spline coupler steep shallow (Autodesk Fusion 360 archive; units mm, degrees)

design "spline coupler steep shallow" references "Haas UMC-750 NGC"
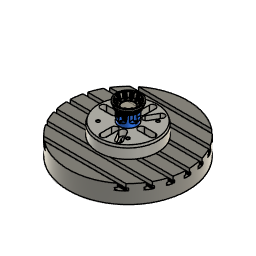
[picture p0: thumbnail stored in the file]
sketch "Sketch1" plane through (0, 0, 0) normal (1, 0, 0) x axis (0, 1, 0)
  line L1 (50.8, 0) -> (0, 0)
  line L2 (50.8, 25.4) -> (50.8, 0)
  line L3 (44.45, 25.4) -> (50.8, 25.4)
  line L4 (37.5164, 6.35) -> (44.45, 25.4)
  line L5 (0, 6.35) -> (37.5164, 6.35)
  line L6 (0, 0) -> (0, 6.35)
  line L7 (50.8, 19.05) -> (50.8, 25.4)
  line L8 (43.8664, 0) -> (50.8, 19.05)
  line L9 (48.0144, 13.7174) -> (48.4888, 12.7)
  line L10 (49.0317, 14.1918) -> (48.0144, 13.7174)
  line L11 (48.7603, 13.4459) -> (48.0144, 13.7174)
  line L12 (46.1776, 6.35) -> (47.0031, 6.35)
  circle C1 centre (48.9975, 12.9372) radius 0.5613
  circle C2 centre (47.0031, 6.35) radius 1.5875
  point P1 (0, 0)
  point P2 (0, 0)
  point P8 (0, 0)
  point P9 (50.8, 19.05)
  point P10 (43.8664, 0)
  point P11 (48.4888, 12.7)
  point P13 (49.0317, 14.1918)
  point P14 (48.7603, 13.4459)
  point P16 (48.4888, 12.7)
  point P17 (48.7603, 13.4459)
  point P18 (47.0031, 6.35)
  point P19 (47.0031, 6.35)
  point P20 (46.1776, 6.35)
  point P3 (50.8, 0)
  point P4 (50.8, 25.4)
  point P7 (0, 6.35)
  point P12 (48.0144, 13.7174)
  point P5 (44.45, 25.4)
  coincident P1 P2
  horizontal L1
  perpendicular L1 L2
  perpendicular L2 L3
  parallel L1 L5
  coincident P1 P8
  vertical L6
  coincident L2 P9
  coincident L1 P10
  parallel L4 L8
  coincident L8 P11
  coincident L8 P13
  perpendicular L9 L10
  equal L9 L10
  coincident L8 P14
  perpendicular L8 L11
  coincident C1 P16
  coincident L8 P16
  coincident P11 P16
  coincident C1 P17
  coincident P14 P17
  tangent L9 C1
  coincident P18 P19
  coincident L8 P20
  horizontal L12
  dimension "d2" = 88.9
  dimension "d3" distance P3 P4 = 25.4
  dimension "d4" angle L3 L4 = 70
  dimension "d5" distance P7 P8 = 6.35
  dimension "d37" distance P4 P9 = 6.35
  dimension "d38" distance P12 P14 = 0.7937
  dimension "d39" distance P10 P11 = 12.7
  dimension "d40" distance P4 P5 = 6.35
  dimension "d43" diameter C2 = 3.175
  dimension "d44" distance L1 P18 = 6.35
  dimension "d45" distance P19 P20 = 0.8255
revolve "Revolve1" sketch "Sketch1" AlongAngle 360
work_plane "WorkPlane1" AlongDistance -3.175
sketch "Sketch2" plane through (0, 0, 22.225) normal (0, 0, 1) x axis (1, 0, 0)
  line L1 (0, 36.9444) -> (0, 0)
  line L2 (3.175, 36.9444) -> (-3.175, 36.9444)
  line L3 (3.175, 32.5535) -> (3.175, 36.9444)
  circle C1 centre (0, 0) radius 43.2944
  circle C2 centre (0, 0) radius 36.9444
  arc A1 centre (10.795, 36.9444) radius 7.62 clockwise from (3.175, 36.9444) to (6.0106, 42.8751)
  arc A2 centre (-10.795, 36.9444) radius 7.62 clockwise from (-6.0106, 42.8751) to (-3.175, 36.9444)
  point P2 (0, 0)
  point P4 (0, 0)
  point P5 (0, 36.9444)
  point P8 (6.0106, 42.8751)
  point P7 (3.175, 36.9444)
  point P13 (-3.175, 36.9444)
  point P12 (-6.0106, 42.8751)
  point P6 (-3.175, 36.9444)
  coincident P2 P4
  coincident C2 P5
  vertical L1
  perpendicular L1 L2
  midpoint P5 L2
  coincident C1 P8
  perpendicular L2 L3
  tangent A1 L3
  symmetric L1 P7 P13
  symmetric L1 P8 P12
  symmetric L1 A1 A2
  dimension "d8" = 6.35
  dimension "d9" distance P6 P7 = 6.35
  dimension "d10" radius A1 = 7.62
sketch "Sketch3" plane through (0, 0, 22.225) normal (0, 0, 1) x axis (1, 0, 0)
sketch "Sketch4" plane through (0, 0, 0) normal (1, 0, 0) x axis (0, 1, 0)
  line L1 (37.5164, 6.35) -> (44.45, 25.4)
  line L2 (-44.45, 25.4) -> (-37.5164, 6.35)
  line L3 (36.9444, 22.225) -> (0, 22.225)
  line L4 (31.1664, 6.35) -> (36.9444, 22.225)
  line L5 (-37.5164, 6.35) -> (37.5164, 6.35)
  point P7 (36.9444, 22.225)
  point P8 (36.9444, 22.225)
  point P9 (31.1664, 6.35)
  coincident P7 P8
  coincident P9 L5
  parallel L1 L4
copy_paste_bodies "CopyPasteBodies2"
sweep "Sweep1" sketch "Sketch2" TwistAngle 0 TaperAngle 0
fillet "Fillet1" sketch "Sketch1" radius 1.5875
fillet "Fillet5" sketch "Sketch1" radius 1.5875
circular_pattern "C-Pattern1" countU 12 TotalAngle 360
fillet "Fillet2" radius 1.5875
fillet "Fillet4" radius 1.5875
sketch "Sketch5" plane through (0, 0, 6.35) normal (0, 0, 1) x axis (-1, 0, 0)
  curve K1 (12.3507, -34.2457) -> (12.1885, -30.8252)
  line L1 (16.5345, -25.1581) -> (13.5203, -26.8984)
  curve K2 (20.6012, -25.9681) -> (23.4823, -27.8189)
  curve K3 (27.8189, -23.4823) -> (25.9681, -20.6012)
  line L2 (26.8984, -13.5203) -> (25.1581, -16.5345)
  curve K4 (30.8252, -12.1885) -> (34.2457, -12.3507)
  curve K5 (35.833, -6.4268) -> (32.7897, -4.8571)
  line L3 (30.0548, 1.7403) -> (30.0548, -1.7403)
  curve K6 (32.7897, 4.8571) -> (35.833, 6.4268)
  curve K7 (34.2457, 12.3507) -> (30.8252, 12.1885)
  line L4 (25.1581, 16.5345) -> (26.8984, 13.5203)
  curve K8 (25.9681, 20.6012) -> (27.8189, 23.4823)
  curve K9 (23.4823, 27.8189) -> (20.6012, 25.9681)
  line L5 (13.5203, 26.8984) -> (16.5345, 25.1581)
  curve K10 (12.1885, 30.8252) -> (12.3507, 34.2457)
  curve K11 (6.4268, 35.833) -> (4.8571, 32.7897)
  line L6 (-1.7403, 30.0548) -> (1.7403, 30.0548)
  curve K12 (-4.8571, 32.7897) -> (-6.4268, 35.833)
  curve K13 (-12.3507, 34.2457) -> (-12.1885, 30.8252)
  line L7 (-16.5345, 25.1581) -> (-13.5203, 26.8984)
  curve K14 (-20.6012, 25.9681) -> (-23.4823, 27.8189)
  curve K15 (-27.8189, 23.4823) -> (-25.9681, 20.6012)
  line L8 (-26.8984, 13.5203) -> (-25.1581, 16.5345)
  curve K16 (-30.8252, 12.1885) -> (-34.2457, 12.3507)
  curve K17 (-35.833, 6.4268) -> (-32.7897, 4.8571)
  line L9 (-30.0548, -1.7403) -> (-30.0548, 1.7403)
  curve K18 (-32.7897, -4.8571) -> (-35.833, -6.4268)
  curve K19 (-34.2457, -12.3507) -> (-30.8252, -12.1885)
  line L10 (-25.1581, -16.5345) -> (-26.8984, -13.5203)
  curve K20 (-25.9681, -20.6012) -> (-27.8189, -23.4823)
  curve K21 (-23.4823, -27.8189) -> (-20.6012, -25.9681)
  line L11 (-13.5203, -26.8984) -> (-16.5345, -25.1581)
  curve K22 (-12.1885, -30.8252) -> (-12.3507, -34.2457)
  curve K23 (-6.4268, -35.833) -> (-4.8571, -32.7897)
  line L12 (1.7403, -30.0548) -> (-1.7403, -30.0548)
  curve K24 (4.8571, -32.7897) -> (6.4268, -35.833)
  closed curve K25 centre (15.2096, -29.8245)
  closed curve K26 centre (18.2239, -28.0842)
  arc A1 centre (0, 0) radius 36.4048 clockwise from (27.8189, -23.4823) to (23.4823, -27.8189)
  closed curve K27 centre (28.0842, -18.2239)
  closed curve K28 centre (29.8245, -15.2096)
  arc A2 centre (0, 0) radius 36.4048 clockwise from (35.833, -6.4268) to (34.2457, -12.3507)
  closed curve K29 centre (33.4336, -1.7403)
  closed curve K30 centre (33.4336, 1.7403)
  arc A3 centre (0, 0) radius 36.4048 clockwise from (34.2457, 12.3507) to (35.833, 6.4268)
  closed curve K31 centre (29.8245, 15.2096)
  closed curve K32 centre (28.0842, 18.2239)
  arc A4 centre (0, 0) radius 36.4048 clockwise from (23.4823, 27.8189) to (27.8189, 23.4823)
  closed curve K33 centre (18.2239, 28.0842)
  closed curve K34 centre (15.2096, 29.8245)
  arc A5 centre (0, 0) radius 36.4048 clockwise from (6.4268, 35.833) to (12.3507, 34.2457)
  closed curve K35 centre (1.7403, 33.4336)
  closed curve K36 centre (-1.7403, 33.4336)
  arc A6 centre (0, 0) radius 36.4048 clockwise from (-12.3507, 34.2457) to (-6.4268, 35.833)
  closed curve K37 centre (-15.2096, 29.8245)
  closed curve K38 centre (-18.2239, 28.0842)
  arc A7 centre (0, 0) radius 36.4048 clockwise from (-27.8189, 23.4823) to (-23.4823, 27.8189)
  closed curve K39 centre (-28.0842, 18.2239)
  closed curve K40 centre (-29.8245, 15.2096)
  arc A8 centre (0, 0) radius 36.4048 clockwise from (-35.833, 6.4268) to (-34.2457, 12.3507)
  closed curve K41 centre (-33.4336, 1.7403)
  closed curve K42 centre (-33.4336, -1.7403)
  arc A9 centre (0, 0) radius 36.4048 clockwise from (-34.2457, -12.3507) to (-35.833, -6.4268)
  closed curve K43 centre (-29.8245, -15.2096)
  closed curve K44 centre (-28.0842, -18.2239)
  arc A10 centre (0, 0) radius 36.4048 clockwise from (-23.4823, -27.8189) to (-27.8189, -23.4823)
  closed curve K45 centre (-18.2239, -28.0842)
  closed curve K46 centre (-15.2096, -29.8245)
  arc A11 centre (0, 0) radius 36.4048 clockwise from (-6.4268, -35.833) to (-12.3507, -34.2457)
  closed curve K47 centre (-1.7403, -33.4336)
  closed curve K48 centre (1.7403, -33.4336)
  arc A12 centre (0, 0) radius 36.4048 clockwise from (12.3507, -34.2457) to (6.4268, -35.833)
  circle C1 centre (0, 0) radius 25.4
  concentric A1 C1
  dimension "d29" diameter C1 = 50.8
extrude "Extrude1" cut sketch "Sketch5" profile of C1 against normal blind 3.175
chamfer "Chamfer1" sketch "Sketch1" distance 0.7937
fillet "Fillet6" sketch "Sketch1" radius 1.5875
delete_face "DeleteFace1"
delete_face "DeleteFace2"
delete_face "DeleteFace3"
derived_base_feature "Derived Base Feature1" bodies "Dovetail"
move "Move1"
offset_faces "OffsetFaces1" distance -25.4
move "Move2"
align "Align1"
combine "Combine2" bodies "Dovetail"
derived_base_feature "Derived Base Feature1" bodies "Body1"
base_feature "Base Feature1"
joint "Assemble1" alignAngle 0 alignOffsetX 0 named "d2_1" alignOffsetY 0 named "d3_1" alignOffsetZ 0 named "d4_1"
base_feature "Base Feature1" bodies "Body1", "Body2", "Body3", "Body4", "Body5", "Body6"
joint "Assemble2" alignAngle 0 named "d5_1" alignOffsetX 0 named "d6_1" alignOffsetY 0 named "d7_1" alignOffsetZ 0 named "d8_1"
joint "Assemble1" alignAngle 0 alignOffsetX 0 alignOffsetY 0 alignOffsetZ 0
sketch "Sketch7" plane through (0, 0, 0) normal (1, 0, 0) x axis (0, 1, 0)
  line L1 (-251.1903, -101.5746) -> (-198.6319, -101.5746)
  point P1 (0, 0)
  point P2 (0, -355.5746)
  vertical P1 P2
  dimension "d51" distance P2 L1 = 254
work_point "WorkPoint1"
sketch "Dovetail" plane through (0, 0, 0) normal (1, 0, 0) x axis (0, 1, 0)
  line L1 (-18.5336, -2.3876) -> (-17.1551, 0)
  line L2 (-18.5336, -3.1496) -> (-18.5336, -2.3876)
  line L3 (-23.5051, 0) -> (-17.1551, 0)
  line L4 (-23.5051, -50.8) -> (-23.5051, 0)
  line L5 (-18.5336, -50.8) -> (-23.5051, -50.8)
  line L6 (-18.5336, -3.1496) -> (-18.5336, -50.8)
  point P2 (-17.1551, 0)
  point P6 (-17.1551, 0)
  point P5 (-18.5336, -3.1496)
  point P10 (-18.5336, -3.1496)
  point P7 (-23.5051, 0)
  point P8 (-23.5051, -50.8)
  coincident P2 P6
  horizontal L3
  perpendicular L3 L4
  perpendicular L4 L5
  coincident P5 P10
  vertical L6
  dimension "d52" = 12.7
  dimension "d53" distance P7 P8 = 50.8
sketch "Sketch9" plane through (0, 0, 0) normal (1, 0, 0) x axis (0, 1, 0)
  line L1 (31.5465, 7.3945) -> (36.5642, 21.1805)
revolve "Revolve3" AlongAngle 360
component_insert "Component Insert"
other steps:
base_feature "Base Feature2" bodies "Stock"
joint_origin "JointOrigin1"
create_component "CreateComponent1"
joint_origin "JointOrigin1"
create_component "CreateComponent2"
create_component "CreateComponent2"
create_component "CreateComponent3"
named bodies: "Part", "Stock", "Dovetail", "Body1", "Body2", "Body3", "Body4", "Body5", "Body6"

design "Haas UMC-750 NGC"
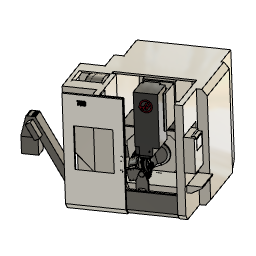
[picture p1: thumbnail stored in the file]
base_feature "Base Feature1"
base_feature "Base Feature1"
base_feature "Base Feature1"
base_feature "Base Feature1"
base_feature "Base Feature1"
base_feature "Base Feature1"
base_feature "Base Feature1"
base_feature "Base Feature1"
base_feature "Base Feature1" bodies "Body1"
base_feature "Base Feature1"
base_feature "Base Feature1" bodies "Body1", "Body2", "Body3", "Body4", "Body5", "Body6"
joint "Assemble1" alignAngle 0 alignOffsetX 0 alignOffsetY 0 alignOffsetZ 0
joint "Assemble2" alignAngle 0 alignOffsetX 0 alignOffsetY 0 alignOffsetZ 0
as_built_joint "As-built1"
as_built_joint "As-built2" OffsetX 0 OffsetY 0 OffsetZ 0 AngleZ 0
as_built_joint "As-built3" OffsetX 0 OffsetY 0 OffsetZ 0 AngleZ 0
ground "Ground1"
ground "Ground2"
sketch "Sketch1" plane through (0, 0, 0) normal (1, 0, 0) x axis (0, 1, 0)
  line L1 (50.8, 0) -> (0, 0)
  line L2 (50.8, 25.4) -> (50.8, 0)
  line L3 (44.45, 25.4) -> (50.8, 25.4)
  line L4 (37.5164, 6.35) -> (44.45, 25.4)
  line L5 (0, 6.35) -> (37.5164, 6.35)
  line L6 (0, 0) -> (0, 6.35)
  line L7 (50.8, 19.05) -> (50.8, 25.4)
  line L8 (43.8664, 0) -> (50.8, 19.05)
  line L9 (48.0144, 13.7174) -> (48.4888, 12.7)
  line L10 (49.0317, 14.1918) -> (48.0144, 13.7174)
  line L11 (48.7603, 13.4459) -> (48.0144, 13.7174)
  line L12 (46.1776, 6.35) -> (47.0031, 6.35)
  circle C1 centre (48.9975, 12.9372) radius 0.5613
  circle C2 centre (47.0031, 6.35) radius 1.5875
  point P1 (0, 0)
  point P2 (0, 0)
  point P8 (0, 0)
  point P9 (50.8, 19.05)
  point P10 (43.8664, 0)
  point P11 (48.4888, 12.7)
  point P13 (49.0317, 14.1918)
  point P14 (48.7603, 13.4459)
  point P16 (48.4888, 12.7)
  point P17 (48.7603, 13.4459)
  point P18 (47.0031, 6.35)
  point P19 (47.0031, 6.35)
  point P20 (46.1776, 6.35)
  point P3 (50.8, 0)
  point P4 (50.8, 25.4)
  point P7 (0, 6.35)
  point P12 (48.0144, 13.7174)
  point P5 (44.45, 25.4)
  coincident P1 P2
  horizontal L1
  perpendicular L1 L2
  perpendicular L2 L3
  parallel L1 L5
  coincident P1 P8
  vertical L6
  coincident L2 P9
  coincident L1 P10
  parallel L4 L8
  coincident L8 P11
  coincident L8 P13
  perpendicular L9 L10
  equal L9 L10
  coincident L8 P14
  perpendicular L8 L11
  coincident C1 P16
  coincident L8 P16
  coincident P11 P16
  coincident C1 P17
  coincident P14 P17
  tangent L9 C1
  coincident P18 P19
  coincident L8 P20
  horizontal L12
  dimension "d2_1" = 88.9
  dimension "d3_1" distance P3 P4 = 25.4
  dimension "d4_1" angle L3 L4 = 70
  dimension "d5_1" distance P7 P8 = 6.35
  dimension "d37" distance P4 P9 = 6.35
  dimension "d38" distance P12 P14 = 0.7937
  dimension "d39" distance P10 P11 = 12.7
  dimension "d40" distance P4 P5 = 6.35
  dimension "d43" diameter C2 = 3.175
  dimension "d44" distance L1 P18 = 6.35
  dimension "d45" distance P19 P20 = 0.8255
revolve "Revolve1" sketch "Sketch1" AlongAngle 360 named "d6_1"
work_plane "WorkPlane1" AlongDistance -3.175 named "d7_1"
sketch "Sketch2" plane through (0, 0, 22.225) normal (0, 0, 1) x axis (1, 0, 0)
  line L1 (0, 36.9444) -> (0, 0)
  line L2 (3.175, 36.9444) -> (-3.175, 36.9444)
  line L3 (3.175, 32.5535) -> (3.175, 36.9444)
  circle C1 centre (0, 0) radius 43.2944
  circle C2 centre (0, 0) radius 36.9444
  arc A1 centre (10.795, 36.9444) radius 7.62 clockwise from (3.175, 36.9444) to (6.0106, 42.8751)
  arc A2 centre (-10.795, 36.9444) radius 7.62 clockwise from (-6.0106, 42.8751) to (-3.175, 36.9444)
  point P2 (0, 0)
  point P4 (0, 0)
  point P5 (0, 36.9444)
  point P8 (6.0106, 42.8751)
  point P7 (3.175, 36.9444)
  point P13 (-3.175, 36.9444)
  point P12 (-6.0106, 42.8751)
  point P6 (-3.175, 36.9444)
  coincident P2 P4
  coincident C2 P5
  vertical L1
  perpendicular L1 L2
  midpoint P5 L2
  coincident C1 P8
  perpendicular L2 L3
  tangent A1 L3
  symmetric L1 P7 P13
  symmetric L1 P8 P12
  symmetric L1 A1 A2
  dimension "d8_1" = 6.35
  dimension "d9_1" distance P6 P7 = 6.35
  dimension "d10_1" radius A1 = 7.62
sketch "Sketch3" plane through (0, 0, 22.225) normal (0, 0, 1) x axis (1, 0, 0)
sketch "Sketch4" plane through (0, 0, 0) normal (1, 0, 0) x axis (0, 1, 0)
  line L1 (37.5164, 6.35) -> (44.45, 25.4)
  line L2 (-44.45, 25.4) -> (-37.5164, 6.35)
  line L3 (36.9444, 22.225) -> (0, 22.225)
  line L4 (31.1664, 6.35) -> (36.9444, 22.225)
  line L5 (-37.5164, 6.35) -> (37.5164, 6.35)
  point P7 (36.9444, 22.225)
  point P8 (36.9444, 22.225)
  point P9 (31.1664, 6.35)
  coincident P7 P8
  coincident P9 L5
  parallel L1 L4
copy_paste_bodies "CopyPasteBodies2"
sweep "Sweep1" sketch "Sketch2" TwistAngle 0 named "d15_1" TaperAngle 0 named "d16_1"
fillet "Fillet1" radius 1.5875
fillet "Fillet5" radius 1.5875
circular_pattern "C-Pattern1" countU 12 TotalAngle 360
fillet "Fillet2" radius 1.5875
fillet "Fillet4" radius 1.5875
sketch "Sketch5" plane through (0, 0, 6.35) normal (0, 0, 1) x axis (-1, 0, 0)
  curve K1 (12.3507, -34.2457) -> (12.1885, -30.8252)
  line L1 (16.5345, -25.1581) -> (13.5203, -26.8984)
  curve K2 (20.6012, -25.9681) -> (23.4823, -27.8189)
  curve K3 (27.8189, -23.4823) -> (25.9681, -20.6012)
  line L2 (26.8984, -13.5203) -> (25.1581, -16.5345)
  curve K4 (30.8252, -12.1885) -> (34.2457, -12.3507)
  curve K5 (35.833, -6.4268) -> (32.7897, -4.8571)
  line L3 (30.0548, 1.7403) -> (30.0548, -1.7403)
  curve K6 (32.7897, 4.8571) -> (35.833, 6.4268)
  curve K7 (34.2457, 12.3507) -> (30.8252, 12.1885)
  line L4 (25.1581, 16.5345) -> (26.8984, 13.5203)
  curve K8 (25.9681, 20.6012) -> (27.8189, 23.4823)
  curve K9 (23.4823, 27.8189) -> (20.6012, 25.9681)
  line L5 (13.5203, 26.8984) -> (16.5345, 25.1581)
  curve K10 (12.1885, 30.8252) -> (12.3507, 34.2457)
  curve K11 (6.4268, 35.833) -> (4.8571, 32.7897)
  line L6 (-1.7403, 30.0548) -> (1.7403, 30.0548)
  curve K12 (-4.8571, 32.7897) -> (-6.4268, 35.833)
  curve K13 (-12.3507, 34.2457) -> (-12.1885, 30.8252)
  line L7 (-16.5345, 25.1581) -> (-13.5203, 26.8984)
  curve K14 (-20.6012, 25.9681) -> (-23.4823, 27.8189)
  curve K15 (-27.8189, 23.4823) -> (-25.9681, 20.6012)
  line L8 (-26.8984, 13.5203) -> (-25.1581, 16.5345)
  curve K16 (-30.8252, 12.1885) -> (-34.2457, 12.3507)
  curve K17 (-35.833, 6.4268) -> (-32.7897, 4.8571)
  line L9 (-30.0548, -1.7403) -> (-30.0548, 1.7403)
  curve K18 (-32.7897, -4.8571) -> (-35.833, -6.4268)
  curve K19 (-34.2457, -12.3507) -> (-30.8252, -12.1885)
  line L10 (-25.1581, -16.5345) -> (-26.8984, -13.5203)
  curve K20 (-25.9681, -20.6012) -> (-27.8189, -23.4823)
  curve K21 (-23.4823, -27.8189) -> (-20.6012, -25.9681)
  line L11 (-13.5203, -26.8984) -> (-16.5345, -25.1581)
  curve K22 (-12.1885, -30.8252) -> (-12.3507, -34.2457)
  curve K23 (-6.4268, -35.833) -> (-4.8571, -32.7897)
  line L12 (1.7403, -30.0548) -> (-1.7403, -30.0548)
  curve K24 (4.8571, -32.7897) -> (6.4268, -35.833)
  closed curve K25 centre (15.2096, -29.8245)
  closed curve K26 centre (18.2239, -28.0842)
  arc A1 centre (0, 0) radius 36.4048 clockwise from (27.8189, -23.4823) to (23.4823, -27.8189)
  closed curve K27 centre (28.0842, -18.2239)
  closed curve K28 centre (29.8245, -15.2096)
  arc A2 centre (0, 0) radius 36.4048 clockwise from (35.833, -6.4268) to (34.2457, -12.3507)
  closed curve K29 centre (33.4336, -1.7403)
  closed curve K30 centre (33.4336, 1.7403)
  arc A3 centre (0, 0) radius 36.4048 clockwise from (34.2457, 12.3507) to (35.833, 6.4268)
  closed curve K31 centre (29.8245, 15.2096)
  closed curve K32 centre (28.0842, 18.2239)
  arc A4 centre (0, 0) radius 36.4048 clockwise from (23.4823, 27.8189) to (27.8189, 23.4823)
  closed curve K33 centre (18.2239, 28.0842)
  closed curve K34 centre (15.2096, 29.8245)
  arc A5 centre (0, 0) radius 36.4048 clockwise from (6.4268, 35.833) to (12.3507, 34.2457)
  closed curve K35 centre (1.7403, 33.4336)
  closed curve K36 centre (-1.7403, 33.4336)
  arc A6 centre (0, 0) radius 36.4048 clockwise from (-12.3507, 34.2457) to (-6.4268, 35.833)
  closed curve K37 centre (-15.2096, 29.8245)
  closed curve K38 centre (-18.2239, 28.0842)
  arc A7 centre (0, 0) radius 36.4048 clockwise from (-27.8189, 23.4823) to (-23.4823, 27.8189)
  closed curve K39 centre (-28.0842, 18.2239)
  closed curve K40 centre (-29.8245, 15.2096)
  arc A8 centre (0, 0) radius 36.4048 clockwise from (-35.833, 6.4268) to (-34.2457, 12.3507)
  closed curve K41 centre (-33.4336, 1.7403)
  closed curve K42 centre (-33.4336, -1.7403)
  arc A9 centre (0, 0) radius 36.4048 clockwise from (-34.2457, -12.3507) to (-35.833, -6.4268)
  closed curve K43 centre (-29.8245, -15.2096)
  closed curve K44 centre (-28.0842, -18.2239)
  arc A10 centre (0, 0) radius 36.4048 clockwise from (-23.4823, -27.8189) to (-27.8189, -23.4823)
  closed curve K45 centre (-18.2239, -28.0842)
  closed curve K46 centre (-15.2096, -29.8245)
  arc A11 centre (0, 0) radius 36.4048 clockwise from (-6.4268, -35.833) to (-12.3507, -34.2457)
  closed curve K47 centre (-1.7403, -33.4336)
  closed curve K48 centre (1.7403, -33.4336)
  arc A12 centre (0, 0) radius 36.4048 clockwise from (12.3507, -34.2457) to (6.4268, -35.833)
  circle C1 centre (0, 0) radius 25.4
  concentric A1 C1
  dimension "d29" diameter C1 = 50.8
extrude "Extrude1" cut sketch "Sketch5" profile of C1 against normal blind 3.175
chamfer "Chamfer1" distance 0.7937
fillet "Fillet6" radius 1.5875
delete_face "DeleteFace1"
delete_face "DeleteFace2"
delete_face "DeleteFace3"
derived_base_feature "Derived Base Feature1" bodies "Dovetail"
move "Move1"
offset_faces "OffsetFaces1" distance -25.4
move "Move2"
align "Align1"
combine "Combine2" bodies "Dovetail"
derived_base_feature "Derived Base Feature1" bodies "Body1"
base_feature "Base Feature1"
joint "Assemble1" alignAngle 0 named "d1_1" alignOffsetX 0 named "d2_1" alignOffsetY 0 named "d3_1" alignOffsetZ 0 named "d4_1"
base_feature "Base Feature1" bodies "Body1", "Body2", "Body3", "Body4", "Body5", "Body6"
joint "Assemble2" alignAngle 0 named "d5_1" alignOffsetX 0 named "d6_1" alignOffsetY 0 named "d7_1" alignOffsetZ 0 named "d8_1"
joint "Assemble1" alignAngle 0 alignOffsetX 0 alignOffsetY 0 alignOffsetZ 0
sketch "Sketch7" plane through (0, 0, 0) normal (1, 0, 0) x axis (0, 1, 0)
  line L1 (-251.1903, -101.5746) -> (-198.6319, -101.5746)
  point P1 (0, 0)
  point P2 (0, -355.5746)
  vertical P1 P2
  dimension "d51" distance P2 L1 = 254
work_point "WorkPoint1"
sketch "Dovetail" plane through (0, 0, 0) normal (1, 0, 0) x axis (0, 1, 0)
  line L1 (-18.5336, -2.3876) -> (-17.1551, 0)
  line L2 (-18.5336, -3.1496) -> (-18.5336, -2.3876)
  line L3 (-23.5051, 0) -> (-17.1551, 0)
  line L4 (-23.5051, -50.8) -> (-23.5051, 0)
  line L5 (-18.5336, -50.8) -> (-23.5051, -50.8)
  line L6 (-18.5336, -3.1496) -> (-18.5336, -50.8)
  point P2 (-17.1551, 0)
  point P6 (-17.1551, 0)
  point P5 (-18.5336, -3.1496)
  point P10 (-18.5336, -3.1496)
  point P7 (-23.5051, 0)
  point P8 (-23.5051, -50.8)
  coincident P2 P6
  horizontal L3
  perpendicular L3 L4
  perpendicular L4 L5
  coincident P5 P10
  vertical L6
  dimension "d52" = 12.7
  dimension "d53" distance P7 P8 = 50.8
remove_instance "RemoveInstance2"
as_built_joint "As-built4"
as_built_joint "As-built5" OffsetX 0 OffsetY 0 OffsetZ 0 AngleZ 0
ground "Ground3"
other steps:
base_feature "Base Feature2" bodies "Stock"
create_component "CreateComponent1"
create_component "CreateComponent2"
create_component "CreateComponent3"
create_component "CreateComponent4"
create_component "CreateComponent5"
create_component "CreateComponent6"
create_component "CreateComponent7"
create_component "CreateComponent8"
create_component "CreateComponent1"
create_component "CreateComponent2"
create_component "CreateComponent3"
joint_origin "JointOrigin1"
joint_origin "JointOrigin1"
joint_origin "JointOrigin1"
joint_origin "JointOrigin2"
joint_origin "JointOrigin1"
create_component "CreateComponent1"
joint_origin "JointOrigin1"
create_component "CreateComponent2"
create_component "CreateComponent2"
create_component "CreateComponent3"
create_component "CreateComponent9"
named bodies: "Body1", "Body2", "Body3", "Body4", "Body5", "Body6", "Part", "Stock", "Dovetail"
